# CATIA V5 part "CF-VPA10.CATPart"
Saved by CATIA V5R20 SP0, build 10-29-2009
Part number: CF-VPA10
Bounding box of the stored display mesh (mm): x 0 to 25.5, y -5 to 5, z -5 to 5
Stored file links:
  C:\Users\Utente\Desktop\IO LAVORO\3D X SITO CF\X SITO\PLASTICA\CF-VPA\CF-VPA10.CATPart
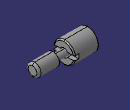
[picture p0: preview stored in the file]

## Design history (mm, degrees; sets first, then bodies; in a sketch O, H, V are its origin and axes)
Set1
  DatumSurface1 to DatumSurface30 "CF-VPA10"
Body1 (main body)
